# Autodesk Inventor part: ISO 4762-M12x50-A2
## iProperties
Created: 2010-05
Part Number: ISO 4762-M12x50-A2
Material: A2
Description: I6kt-Schraube
Document SubType Name: Modeling
Standard: ISO 4762
Designer: M.Fiedler
Standard Revision: Vierte Ausgabe 2004-03-01
Standards Organization: ISO
Language: de-DE
Size Designation: M12 x 50
Categories: <MemberInstance><Categories><Category DisplayName="Verbindungselemente" InternalName="e4da775c-781d-43d5-af7c-5136215cf5a6" Mnemonic="FSTN"><Category DisplayNam
Density: 8.03 g/cm^3
Category: 410 Schraube
IsCustomPart: 0
Author: M.Fiedler
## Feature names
1. Körper [Revolution]
2. Loch [Extrusion]
3. Rundung1 [Fillet]
4. Fase1 [Chamfer]
5. Fillet2
